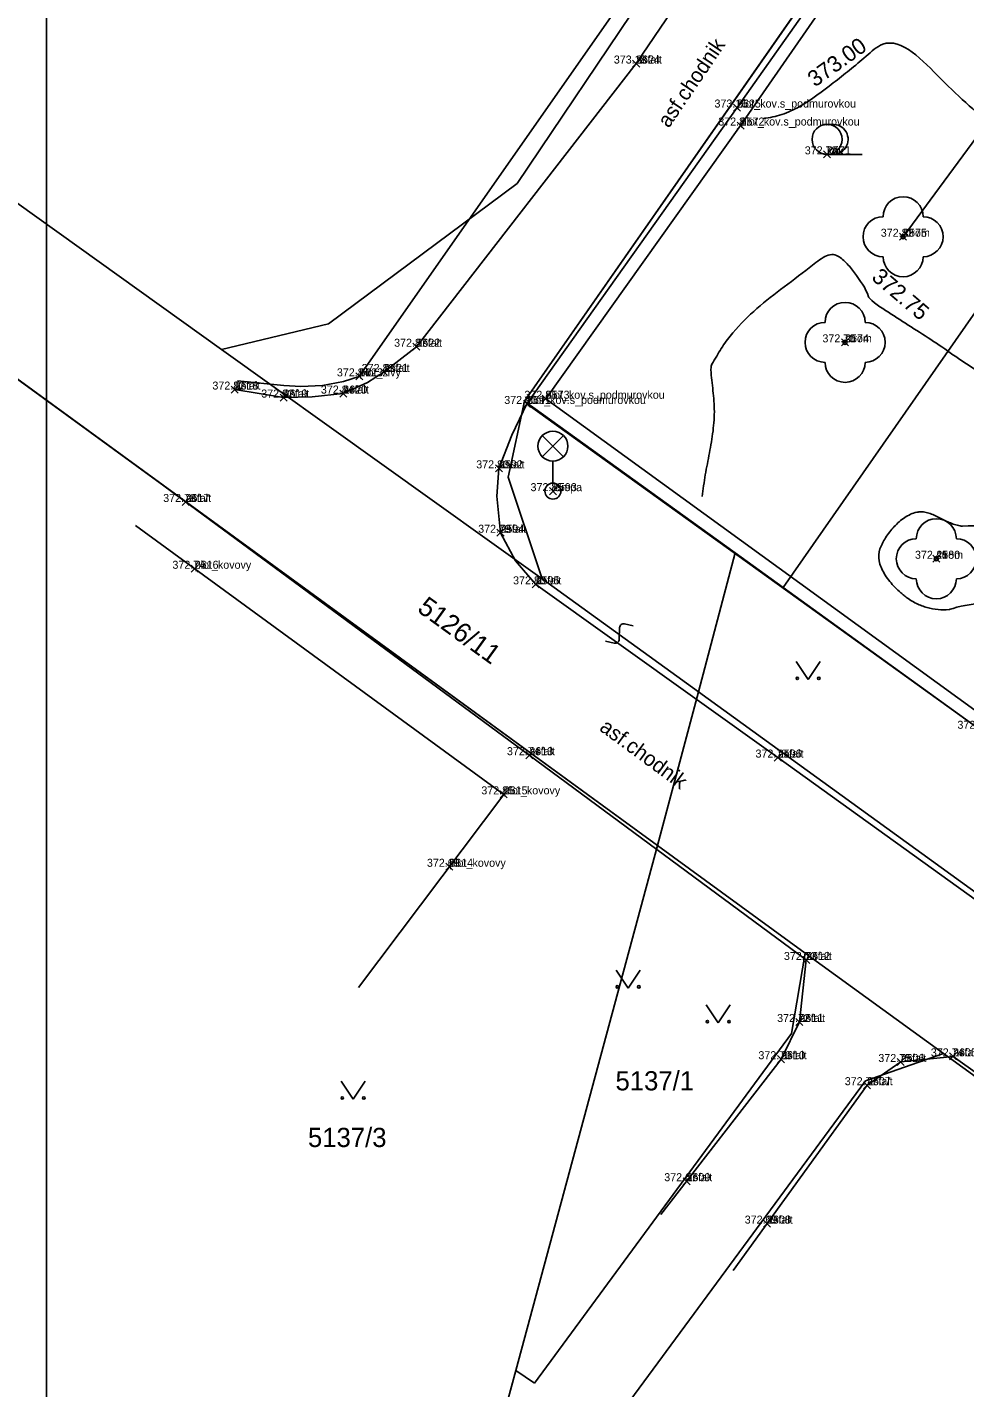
# Model space of a CAD drawing. Extents: x -400488 to -400124, y -1251493 to -1251223.
# Drawn here: x -400397.92 to -400374.49, y -1251353.83 to -1251319.82 of the extents above; entities that cross this region are included whole.
import ezdxf

# ---------------------------------------------------------------- set-up
doc = ezdxf.new("R2010")
doc.units = 0
for name, color, linetype in [('Level 20', 7, 'Continuous'), ('Level 21', 7, 'Continuous'), ('Level 22', 7, 'Continuous'), ('Level 23', 7, 'Continuous'), ('Level 3', 7, 'Continuous'), ('Level 32', 7, 'Continuous'), ('Level 35', 7, 'Continuous'), ('Level 36', 7, 'Continuous'), ('Level 49', 7, 'Continuous'), ('Level 53', 7, 'Continuous'), ('Level 63', 7, 'Continuous')]:
    doc.layers.add(name, color=color, linetype=linetype)

msp = doc.modelspace()

# ---------------------------------------------------------------- linework, layer by layer
at = {"layer": 'Level 20'}
for p, q in [((-400382.788, -1251320.818), (-400382.612, -1251320.642)), ((-400382.612, -1251320.818), (-400382.788, -1251320.642)), ((-400380.268, -1251321.918), (-400380.092, -1251321.742)), ((-400380.092, -1251321.918), (-400380.268, -1251321.742)), ((-400380.178, -1251322.368), (-400380.002, -1251322.192)), ((-400380.002, -1251322.368), (-400380.178, -1251322.192)), ((-400378.018, -1251323.088), (-400377.842, -1251322.912)), ((-400377.842, -1251323.088), (-400378.018, -1251322.912)), ((-400376.118, -1251325.148), (-400375.942, -1251324.972)), ((-400375.942, -1251325.148), (-400376.118, -1251324.972)), ((-400377.568, -1251327.788), (-400377.392, -1251327.612)), ((-400377.392, -1251327.788), (-400377.568, -1251327.612)), ((-400388.278, -1251327.898), (-400388.102, -1251327.722)), ((-400388.102, -1251327.898), (-400388.278, -1251327.722)), ((-400389.708, -1251328.638), (-400389.532, -1251328.462)), ((-400389.532, -1251328.638), (-400389.708, -1251328.462)), ((-400389.088, -1251328.528), (-400388.912, -1251328.352)), ((-400388.912, -1251328.528), (-400389.088, -1251328.352)), ((-400392.818, -1251328.968), (-400392.642, -1251328.792)), ((-400392.642, -1251328.968), (-400392.818, -1251328.792)), ((-400391.598, -1251329.168), (-400391.422, -1251328.992)), ((-400391.422, -1251329.168), (-400391.598, -1251328.992)), ((-400390.108, -1251329.068), (-400389.932, -1251328.892)), ((-400389.932, -1251329.068), (-400390.108, -1251328.892)), ((-400385.518, -1251329.328), (-400385.342, -1251329.152)), ((-400385.342, -1251329.328), (-400385.518, -1251329.152)), ((-400385.048, -1251329.198), (-400384.872, -1251329.022)), ((-400384.872, -1251329.198), (-400385.048, -1251329.022)), ((-400386.218, -1251330.938), (-400386.042, -1251330.762)), ((-400386.042, -1251330.938), (-400386.218, -1251330.762)), ((-400384.868, -1251331.508), (-400384.692, -1251331.332)), ((-400384.692, -1251331.508), (-400384.868, -1251331.332)), ((-400394.048, -1251331.778), (-400393.872, -1251331.602)), ((-400393.872, -1251331.778), (-400394.048, -1251331.602)), ((-400386.178, -1251332.548), (-400386.002, -1251332.372)), ((-400386.002, -1251332.548), (-400386.178, -1251332.372)), ((-400375.288, -1251333.198), (-400375.112, -1251333.022)), ((-400375.112, -1251333.198), (-400375.288, -1251333.022)), ((-400393.818, -1251333.448), (-400393.642, -1251333.272)), ((-400393.642, -1251333.448), (-400393.818, -1251333.272)), ((-400385.298, -1251333.838), (-400385.122, -1251333.662)), ((-400385.122, -1251333.838), (-400385.298, -1251333.662)), ((-400385.458, -1251338.108), (-400385.282, -1251337.932)), ((-400385.282, -1251338.108), (-400385.458, -1251337.932)), ((-400379.248, -1251338.168), (-400379.072, -1251337.992)), ((-400379.072, -1251338.168), (-400379.248, -1251337.992)), ((-400386.098, -1251339.088), (-400385.922, -1251338.912)), ((-400385.922, -1251339.088), (-400386.098, -1251338.912)), ((-400387.458, -1251340.898), (-400387.282, -1251340.722)), ((-400387.282, -1251340.898), (-400387.458, -1251340.722)), ((-400378.538, -1251343.228), (-400378.362, -1251343.052)), ((-400378.362, -1251343.228), (-400378.538, -1251343.052)), ((-400378.708, -1251344.778), (-400378.532, -1251344.602)), ((-400378.532, -1251344.778), (-400378.708, -1251344.602)), ((-400379.168, -1251345.708), (-400378.992, -1251345.532)), ((-400378.992, -1251345.708), (-400379.168, -1251345.532)), ((-400376.178, -1251345.778), (-400376.002, -1251345.602)), ((-400376.002, -1251345.778), (-400376.178, -1251345.602)), ((-400374.868, -1251345.638), (-400374.692, -1251345.462)), ((-400374.692, -1251345.638), (-400374.868, -1251345.462)), ((-400377.018, -1251346.358), (-400376.842, -1251346.182)), ((-400376.842, -1251346.358), (-400377.018, -1251346.182)), ((-400381.528, -1251348.758), (-400381.352, -1251348.582)), ((-400381.352, -1251348.758), (-400381.528, -1251348.582)), ((-400379.518, -1251349.818), (-400379.342, -1251349.642)), ((-400379.342, -1251349.818), (-400379.518, -1251349.642))]:
    msp.add_line(p, q, dxfattribs=at)
at = {"layer": 'Level 3'}
msp.add_lwpolyline([(-400397.431, -1251233.087), (-400250.431, -1251233.087), (-400250.431, -1251440.987), (-400397.431, -1251440.987)], close=True, dxfattribs=at)
at = {"layer": 'Level 32'}
for points in [[(-400392.73, -1251328.88), (-400391.51, -1251329.08), (-400390.794, -1251329.059), (-400390.02, -1251328.98), (-400389.409, -1251328.705), (-400389, -1251328.44), (-400388.19, -1251327.81), (-400382.7, -1251320.73), (-400372.96, -1251306.38), (-400366.56, -1251297.2), (-400366.487, -1251296.989), (-400366.185, -1251295.472), (-400366.11, -1251294.75), (-400366.12, -1251294.52), (-400366.6, -1251293.882), (-400367.07, -1251293.38)], [(-400385.43, -1251329.24), (-400385.81, -1251330.02), (-400386.13, -1251330.85), (-400386.185, -1251331.545), (-400386.09, -1251332.46), (-400385.712, -1251333.158), (-400385.21, -1251333.75), (-400379.16, -1251338.08), (-400353.86, -1251356.29)], [(-400382.086, -1251349.504), (-400379.08, -1251345.62), (-400378.62, -1251344.69), (-400378.45, -1251343.14), (-400385.37, -1251338.02), (-400394.505, -1251331.289)], [(-400365.68, -1251352.04), (-400374.78, -1251345.55), (-400376.09, -1251345.69), (-400376.93, -1251346.27), (-400380.278, -1251350.903)]]:
    msp.add_lwpolyline(points, dxfattribs=at)
at = {"layer": 'Level 35'}
for points in [[(-400380.18, -1251321.83), (-400371.19, -1251309.1), (-400359.12, -1251291.4)], [(-400343.3, -1251302.69), (-400343.6, -1251302.78), (-400345.93, -1251301.42), (-400359.09, -1251291.97), (-400380.09, -1251322.28), (-400384.96, -1251329.11), (-400372.26, -1251338.33), (-400358.88, -1251348.03)], [(-400392.66, -1251328.664), (-400391.502, -1251328.775), (-400391.078, -1251328.805), (-400390.539, -1251328.775), (-400390.012, -1251328.676), (-400389.62, -1251328.55), (-400374.42, -1251306.82)], [(-400380.18, -1251321.83), (-400385.43, -1251329.24), (-400374.14, -1251337.36)], [(-400389.639, -1251343.829), (-400386.01, -1251339), (-400395.212, -1251332.277)]]:
    msp.add_lwpolyline(points, dxfattribs=at)
at = {"layer": 'Level 36'}
for p, q in [((-400377.93, -1251323), (-400377.055, -1251323)), ((-400378.406, -1251336.129), (-400378.706, -1251335.679)), ((-400378.406, -1251336.129), (-400378.106, -1251335.679)), ((-400382.903, -1251343.841), (-400383.203, -1251343.391)), ((-400382.903, -1251343.841), (-400382.603, -1251343.391))]:
    msp.add_line(p, q, dxfattribs=at)
msp.add_lwpolyline([(-400361.75, -1251305.66), (-400376.03, -1251325.06)], dxfattribs=at)
for centre, radius in [((-400377.93, -1251322.625), 0.375), ((-400376.03, -1251325.06), 0.05), ((-400377.48, -1251327.7), 0.05), ((-400375.2, -1251333.11), 0.05), ((-400378.676, -1251336.099), 0.03), ((-400378.136, -1251336.099), 0.03), ((-400383.173, -1251343.811), 0.03), ((-400382.633, -1251343.811), 0.03)]:
    msp.add_circle(centre, radius, dxfattribs=at)
for centre, radius, start, end in [((-400377.78, -1251322.625), 0.375, 270, 101.537), ((-400376.03, -1251324.56), 0.5, 0, 180), ((-400376.53, -1251325.06), 0.5, 90, 270), ((-400375.53, -1251325.06), 0.5, 270, 90), ((-400376.03, -1251325.56), 0.5, 180, 0), ((-400377.48, -1251327.2), 0.5, 0, 180), ((-400377.98, -1251327.7), 0.5, 90, 270), ((-400376.98, -1251327.7), 0.5, 270, 90), ((-400377.48, -1251328.2), 0.5, 180, 0), ((-400375.2, -1251332.61), 0.5, 0, 180), ((-400375.7, -1251333.11), 0.5, 90, 270), ((-400374.7, -1251333.11), 0.5, 270, 90), ((-400375.2, -1251333.61), 0.5, 180, 0)]:
    msp.add_arc(centre, radius, start, end, dxfattribs=at)
at = {"layer": 'Level 49'}
for points in [[(-400352.293, -1251323.278), (-400352.826, -1251323.097), (-400352.844, -1251323.089), (-400354.58, -1251322.223), (-400356.287, -1251321.302), (-400358.007, -1251320.393), (-400358.886, -1251319.963), (-400359.784, -1251319.561), (-400359.802, -1251319.557), (-400360.521, -1251319.456), (-400361.243, -1251319.387), (-400361.966, -1251319.353), (-400362.686, -1251319.354), (-400362.706, -1251319.359), (-400363.04, -1251319.588), (-400363.343, -1251319.84), (-400363.891, -1251320.382), (-400364.419, -1251320.929), (-400364.995, -1251321.421), (-400366.014, -1251322.099), (-400366.527, -1251322.437), (-400367.024, -1251322.796), (-400367.495, -1251323.197), (-400367.955, -1251323.654), (-400368.388, -1251324.135), (-400368.82, -1251324.624), (-400370.184, -1251324.602), (-400371.084, -1251324.11), (-400371.985, -1251323.601), (-400372.84, -1251323.028), (-400374.376, -1251321.785), (-400375.093, -1251321.106), (-400376.539, -1251320.249), (-400376.957, -1251320.548), (-400377.775, -1251321.215), (-400378.615, -1251321.804), (-400379.061, -1251322.005), (-400379.52, -1251322.108)], [(-400360.059, -1251327.678), (-400360.984, -1251327.116), (-400361.481, -1251326.924), (-400361.997, -1251326.766), (-400362.647, -1251326.609), (-400363.307, -1251326.513), (-400363.966, -1251326.487), (-400364.614, -1251326.544), (-400365.286, -1251326.717), (-400365.924, -1251327.037), (-400366.016, -1251327.112), (-400366.157, -1251327.262), (-400366.291, -1251327.417), (-400366.426, -1251327.572), (-400366.568, -1251327.721), (-400366.592, -1251327.74), (-400367.391, -1251328.187), (-400368.214, -1251328.56), (-400369.056, -1251328.89), (-400369.909, -1251329.209), (-400370.586, -1251329.453), (-400371.283, -1251329.655), (-400371.981, -1251329.763), (-400372.324, -1251329.766), (-400372.492, -1251329.752), (-400372.659, -1251329.727), (-400372.679, -1251329.713), (-400372.684, -1251329.706), (-400374.646, -1251328.105), (-400375.197, -1251327.721), (-400375.761, -1251327.359), (-400376.325, -1251326.993), (-400376.872, -1251326.594), (-400376.885, -1251326.578), (-400376.891, -1251326.563), (-400377.245, -1251325.962), (-400377.456, -1251325.708), (-400377.571, -1251325.606), (-400377.694, -1251325.526), (-400377.853, -1251325.508), (-400378.029, -1251325.58), (-400378.376, -1251325.834), (-400379.092, -1251326.38), (-400379.762, -1251326.927), (-400380.351, -1251327.544), (-400380.604, -1251327.9), (-400380.718, -1251328.094), (-400380.823, -1251328.299), (-400380.827, -1251328.322), (-400380.814, -1251328.583), (-400380.788, -1251328.844), (-400380.761, -1251329.104), (-400380.747, -1251329.365), (-400380.78, -1251329.914), (-400380.868, -1251330.463), (-400380.972, -1251331.01), (-400381.053, -1251331.557)], [(-400363.714, -1251343.002), (-400363.673, -1251343.023), (-400363.375, -1251343.136), (-400363.058, -1251343.199), (-400362.735, -1251343.215), (-400362.576, -1251343.207), (-400362.42, -1251343.189), (-400362.197, -1251343.136), (-400361.985, -1251343.041), (-400361.794, -1251342.898), (-400361.708, -1251342.807), (-400361.668, -1251342.756), (-400361.631, -1251342.702), (-400361.628, -1251342.688), (-400361.629, -1251342.668), (-400361.558, -1251342.35), (-400361.462, -1251342.038), (-400361.221, -1251341.426), (-400360.963, -1251340.819), (-400360.844, -1251340.514), (-400360.742, -1251340.206), (-400360.734, -1251340.149), (-400360.797, -1251340.081), (-400360.861, -1251340.015), (-400360.993, -1251339.887), (-400361.267, -1251339.646), (-400361.844, -1251339.205), (-400362.434, -1251338.782), (-400362.724, -1251338.564), (-400363.006, -1251338.335), (-400363.413, -1251337.986), (-400366.054, -1251335.666), (-400368.695, -1251333.356), (-400368.971, -1251333.145), (-400369.117, -1251333.049), (-400369.267, -1251332.953), (-400369.402, -1251332.894), (-400369.449, -1251332.899), (-400369.496, -1251332.914), (-400369.542, -1251332.932), (-400369.589, -1251332.949), (-400369.637, -1251332.961), (-400369.867, -1251332.972), (-400371.037, -1251332.835), (-400372.205, -1251332.618), (-400373.374, -1251332.408), (-400374.548, -1251332.292), (-400374.561, -1251332.293), (-400374.604, -1251332.288), (-400374.744, -1251332.254), (-400374.882, -1251332.2), (-400375.154, -1251332.066), (-400375.422, -1251331.958), (-400375.556, -1251331.936), (-400375.623, -1251331.937), (-400375.656, -1251331.941), (-400375.69, -1251331.947), (-400375.987, -1251332.079), (-400376.252, -1251332.307), (-400376.466, -1251332.583), (-400376.547, -1251332.724), (-400376.581, -1251332.794), (-400376.609, -1251332.861), (-400376.629, -1251333.159), (-400376.502, -1251333.478), (-400376.267, -1251333.788), (-400376.122, -1251333.931), (-400376.045, -1251333.997), (-400375.965, -1251334.06), (-400375.698, -1251334.227), (-400375.429, -1251334.332), (-400375.158, -1251334.381), (-400374.883, -1251334.379), (-400374.853, -1251334.374), (-400374.783, -1251334.353), (-400373.964, -1251334.213), (-400373.114, -1251334.214), (-400372.299, -1251334.45), (-400371.926, -1251334.686), (-400371.751, -1251334.838), (-400371.667, -1251334.923), (-400371.626, -1251334.968), (-400371.586, -1251335.015), (-400371.472, -1251335.173), (-400371.392, -1251335.331), (-400371.323, -1251335.651), (-400371.467, -1251336.298), (-400371.828, -1251336.953), (-400372.031, -1251337.283), (-400372.216, -1251337.615)]]:
    msp.add_spline(points, degree=3, dxfattribs=at)
at = {"layer": 'Level 53'}
for p, q in [((-400385.045, -1251330.56), (-400384.515, -1251330.03)), ((-400384.515, -1251330.03), (-400385.045, -1251330.56)), ((-400384.515, -1251330.56), (-400385.045, -1251330.03)), ((-400384.78, -1251330.67), (-400384.78, -1251331.22))]:
    msp.add_line(p, q, dxfattribs=at)
for centre, radius in [((-400384.78, -1251330.295), 0.375), ((-400384.78, -1251331.42), 0.2)]:
    msp.add_circle(centre, radius, dxfattribs=at)
at = {"layer": 'Level 63'}
for p, q in [((-400352.67, -1251296), (-400379.03, -1251333.83)), ((-400379.03, -1251333.83), (-400352.67, -1251296)), ((-400377.14, -1251311.01), (-400385.67, -1251323.73)), ((-400385.49, -1251329.17), (-400375.65, -1251315.05)), ((-400375.65, -1251315.05), (-400385.49, -1251329.17)), ((-400403.53, -1251320.38), (-400393.06, -1251327.88)), ((-400393.06, -1251327.88), (-400403.53, -1251320.38)), ((-400405.54, -1251323.24), (-400382.17, -1251340.28)), ((-400382.17, -1251340.28), (-400405.54, -1251323.24)), ((-400385.67, -1251323.73), (-400390.39, -1251327.24)), ((-400390.39, -1251327.24), (-400393.06, -1251327.88)), ((-400393.06, -1251327.88), (-400385.05, -1251333.61)), ((-400385.05, -1251333.61), (-400393.06, -1251327.88)), ((-400385.9, -1251331.07), (-400385.49, -1251329.17)), ((-400385.49, -1251329.17), (-400385.9, -1251331.07)), ((-400380.23, -1251332.96), (-400385.49, -1251329.17)), ((-400385.49, -1251329.17), (-400380.23, -1251332.96)), ((-400385.05, -1251333.61), (-400385.9, -1251331.07)), ((-400385.9, -1251331.07), (-400385.05, -1251333.61)), ((-400380.23, -1251332.96), (-400381.14, -1251336.44)), ((-400381.14, -1251336.44), (-400380.23, -1251332.96)), ((-400379.03, -1251333.83), (-400380.23, -1251332.96)), ((-400380.23, -1251332.96), (-400379.03, -1251333.83)), ((-400385.05, -1251333.61), (-400381.14, -1251336.44)), ((-400362.18, -1251345.99), (-400379.03, -1251333.83)), ((-400379.03, -1251333.83), (-400362.18, -1251345.99)), ((-400382.992, -1251334.738), (-400382.774, -1251334.785)), ((-400383.124, -1251335.125), (-400383.113, -1251334.832)), ((-400383.463, -1251335.172), (-400383.246, -1251335.219)), ((-400381.14, -1251336.44), (-400382.17, -1251340.28)), ((-400382.17, -1251340.28), (-400381.14, -1251336.44)), ((-400381.14, -1251336.44), (-400338.44, -1251367.39)), ((-400382.17, -1251340.28), (-400385.71, -1251353.4)), ((-400385.71, -1251353.4), (-400382.17, -1251340.28)), ((-400378.48, -1251342.97), (-400382.17, -1251340.28)), ((-400382.17, -1251340.28), (-400378.48, -1251342.97)), ((-400378.48, -1251342.97), (-400378.82, -1251344.98)), ((-400375.02, -1251345.48), (-400378.48, -1251342.97)), ((-400378.48, -1251342.97), (-400375.02, -1251345.48)), ((-400380.95, -1251344.26), (-400380.65, -1251344.71)), ((-400380.65, -1251344.71), (-400380.35, -1251344.26)), ((-400378.82, -1251344.98), (-400385.24, -1251353.72)), ((-400375.02, -1251345.48), (-400376.97, -1251346.16)), ((-400376.97, -1251346.16), (-400375.02, -1251345.48)), ((-400364.08, -1251353.39), (-400375.02, -1251345.48)), ((-400375.02, -1251345.48), (-400364.08, -1251353.39)), ((-400390.075, -1251346.17), (-400389.775, -1251346.62)), ((-400389.775, -1251346.62), (-400389.475, -1251346.17)), ((-400376.97, -1251346.16), (-400386.78, -1251359.48)), ((-400386.78, -1251359.48), (-400376.97, -1251346.16)), ((-400385.71, -1251353.4), (-400387.69, -1251360.72)), ((-400387.69, -1251360.72), (-400385.71, -1251353.4)), ((-400385.24, -1251353.72), (-400385.71, -1251353.4))]:
    msp.add_line(p, q, dxfattribs=at)
for centre in [(-400380.92, -1251344.68), (-400380.38, -1251344.68), (-400390.045, -1251346.59), (-400389.505, -1251346.59)]:
    msp.add_circle(centre, 0.03, dxfattribs=at)
for centre, start, end in [((-400383.013, -1251334.835), 77.7527, 177.7631), ((-400383.224, -1251335.121), 257.753, 357.7631)]:
    msp.add_arc(centre, 0.1, start, end, dxfattribs=at)

# ---------------------------------------------------------------- texts
at = {"layer": 'Level 21'}
for s, p in [('2624', (-400382.7, -1251320.73)), ('2625', (-400380.18, -1251321.83)), ('2572', (-400380.09, -1251322.28)), ('2571', (-400377.93, -1251323)), ('2575', (-400376.03, -1251325.06)), ('2622', (-400388.19, -1251327.81)), ('2574', (-400377.48, -1251327.7)), ('2621', (-400389, -1251328.44)), ('2623', (-400389.62, -1251328.55)), ('2618', (-400392.73, -1251328.88)), ('2619', (-400391.51, -1251329.08)), ('2620', (-400390.02, -1251328.98)), ('2573', (-400384.96, -1251329.11)), ('2591', (-400385.43, -1251329.24)), ('2592', (-400386.13, -1251330.85)), ('2593', (-400384.78, -1251331.42)), ('2617', (-400393.96, -1251331.69)), ('2594', (-400386.09, -1251332.46)), ('2580', (-400375.2, -1251333.11)), ('2616', (-400393.73, -1251333.36)), ('2595', (-400385.21, -1251333.75)), ('2613', (-400385.37, -1251338.02)), ('2596', (-400379.16, -1251338.08)), ('2615', (-400386.01, -1251339)), ('2614', (-400387.37, -1251340.81)), ('2612', (-400378.45, -1251343.14)), ('2611', (-400378.62, -1251344.69)), ('2610', (-400379.08, -1251345.62)), ('2606', (-400376.09, -1251345.69)), ('2605', (-400374.78, -1251345.55)), ('2607', (-400376.93, -1251346.27)), ('2609', (-400381.44, -1251348.67)), ('2608', (-400379.43, -1251349.73))]:
    msp.add_text(s, height=0.2, dxfattribs=at).set_placement(p)
at = {"layer": 'Level 22'}
for s, p in [('asfalt', (-400382.7, -1251320.73)), ('plot_kov.s_podmurovkou', (-400380.18, -1251321.83)), ('plot_kov.s_podmurovkou', (-400380.09, -1251322.28)), ('krik', (-400377.93, -1251323)), ('strom', (-400376.03, -1251325.06)), ('asfalt', (-400388.19, -1251327.81)), ('strom', (-400377.48, -1251327.7)), ('asfalt', (-400389, -1251328.44)), ('plot_zivy', (-400389.62, -1251328.55)), ('asfalt', (-400392.73, -1251328.88)), ('asfalt', (-400391.51, -1251329.08)), ('asfalt', (-400390.02, -1251328.98)), ('plot_kov.s_podmurovkou', (-400384.96, -1251329.11)), ('plot_kov.s_podmurovkou', (-400385.43, -1251329.24)), ('asfalt', (-400386.13, -1251330.85)), ('lampa', (-400384.78, -1251331.42)), ('asfalt', (-400393.96, -1251331.69)), ('asfalt', (-400386.09, -1251332.46)), ('strom', (-400375.2, -1251333.11)), ('plot_kovovy', (-400393.73, -1251333.36)), ('asfalt', (-400385.21, -1251333.75)), ('asfalt', (-400385.37, -1251338.02)), ('asfalt', (-400379.16, -1251338.08)), ('plot_kovovy', (-400386.01, -1251339)), ('plot_kovovy', (-400387.37, -1251340.81)), ('asfalt', (-400378.45, -1251343.14)), ('asfalt', (-400378.62, -1251344.69)), ('asfalt', (-400379.08, -1251345.62)), ('asfalt', (-400376.09, -1251345.69)), ('asfalt', (-400374.78, -1251345.55)), ('asfalt', (-400376.93, -1251346.27)), ('asfalt', (-400381.44, -1251348.67)), ('asfalt', (-400379.43, -1251349.73))]:
    msp.add_text(s, height=0.2, dxfattribs=at).set_placement(p)
at = {"layer": 'Level 23'}
for s, p in [('373.18', (-400383.258, -1251320.73)), ('373.16', (-400380.743, -1251321.83)), ('372.87', (-400380.648, -1251322.28)), ('372.78', (-400378.488, -1251323)), ('372.82', (-400376.588, -1251325.06)), ('372.87', (-400388.748, -1251327.81)), ('372.70', (-400378.046, -1251327.7)), ('372.83', (-400389.558, -1251328.44)), ('372.84', (-400390.178, -1251328.55)), ('372.82', (-400393.288, -1251328.88)), ('372.82', (-400392.068, -1251329.08)), ('372.84', (-400390.578, -1251328.98)), ('372.81', (-400385.493, -1251329.11)), ('372.90', (-400385.996, -1251329.24)), ('372.80', (-400386.696, -1251330.85)), ('372.85', (-400385.339, -1251331.42)), ('372.78', (-400394.518, -1251331.69)), ('372.79', (-400386.648, -1251332.46)), ('372.41', (-400375.733, -1251333.11)), ('372.74', (-400394.288, -1251333.36)), ('372.80', (-400385.776, -1251333.75)), ('372.71', (-400374.673, -1251337.36)), ('372.74', (-400385.928, -1251338.02)), ('372.77', (-400379.718, -1251338.08)), ('372.85', (-400386.569, -1251339)), ('372.69', (-400387.928, -1251340.81)), ('372.73', (-400379.008, -1251343.14)), ('372.72', (-400379.178, -1251344.69)), ('372.70', (-400379.646, -1251345.62)), ('372.75', (-400376.649, -1251345.69)), ('372.74', (-400375.338, -1251345.55)), ('372.77', (-400377.488, -1251346.27)), ('372.67', (-400381.998, -1251348.67)), ('372.69', (-400379.988, -1251349.73))]:
    msp.add_text(s, height=0.2, dxfattribs=at).set_placement(p)
at = {"layer": 'Level 32'}
for rotation, p in [(55.8347, (-400381.885, -1251322.36)), (323.6458, (-400383.641, -1251337.385))]:
    msp.add_text('asf.chodnik', height=0.375, rotation=rotation, dxfattribs=at).set_placement(p)
at = {"layer": 'Level 49'}
for s, rotation, p in [('373.00', 35.7016, (-400378.232, -1251321.332)), ('372.75', 319.5761, (-400376.842, -1251326.114))]:
    msp.add_text(s, height=0.4, rotation=rotation, dxfattribs=at).set_placement(p)
at = {"layer": 'Level 63'}
msp.add_text('5126/11', height=0.48, rotation=324.1667, dxfattribs=at).set_placement((-400388.195, -1251334.412))
for s, p in [('5137/1', (-400383.216, -1251346.4)), ('5137/3', (-400390.901, -1251347.816))]:
    msp.add_text(s, height=0.48, dxfattribs=at).set_placement(p)

doc.saveas('drawing.dxf')
